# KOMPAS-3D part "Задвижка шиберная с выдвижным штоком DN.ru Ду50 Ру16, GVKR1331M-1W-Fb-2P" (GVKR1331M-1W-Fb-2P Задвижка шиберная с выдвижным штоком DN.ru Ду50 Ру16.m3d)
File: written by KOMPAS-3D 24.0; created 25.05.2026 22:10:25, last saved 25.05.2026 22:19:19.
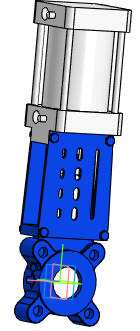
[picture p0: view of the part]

Document properties: Автор: R2D2; Полное имя файла: E:\Работа\Зайцев\GVKR1331M-1W-Fb-2P Задвижка шиберная с выдвижным штоком DN.ru Ду50-300 Ру16-10-6 с пневмоприводом\исходные материалы\DN50\DN50\GVKR1331M-1W-Fb-2P Задвижка шиберная с выдвижным штоком DN.ru Ду50 Ру16.m3d

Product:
- Part/product: Задвижка шиберная с выдвижным штоком DN.ru Ду50 Ру16  | designation GVKR1331M-1W-Fb-2P
    Масса: 7
    Раздел спецификации: Прочие изделия
    Примечание: D040-08791

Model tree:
1. Операция без истории:1

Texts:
  GVKR1331M-1W-Fb-2P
